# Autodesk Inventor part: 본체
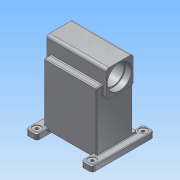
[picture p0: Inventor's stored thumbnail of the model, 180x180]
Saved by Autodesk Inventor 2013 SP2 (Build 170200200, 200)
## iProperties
Created: 2025-06
Part Number: 본체
Material: 알루미늄 6061
Document SubType Name: Modeling
Designer: a
Mass: 8501.84 g
Surface Area: 3573.04 cm^2
Volume: 3137.21 cm^3
Density: 2.71 g/cm^3
Author: a
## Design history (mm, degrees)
sketch "스케치2"
  geometry: L1 (-38, 48)-(38, 48); L2 (48, 38)-(48, -38); L3 (38, -48)-(-38, -48); L4 (-48, -38)-(-48, 38); L5 (-48, 48)-(48, -48); L6 (48, 48)-(-48, -48); L7 (-213, -55)-(-7, -55); L8 (-7, -55)-(-7, 70); L9 (-7, 70)-(-213, 70); L10 (-213, 70)-(-213, -55); A1 r 10 centre (38, 38) between (48, 38) and (38, 48); A2 r 10 centre (-38, 38) between (-38, 48) and (-48, 38); A3 r 10 centre (-38, -38) between (-48, -38) and (-38, -48); A4 r 10 centre (38, -38) between (38, -48) and (48, -38); 1 further point
  constraints: 20 end point, 8 point on circle, 8 point on line, 8 tangent, 4 centre point, 4 parallel, 3 equal radius, 2 horizontal, 2 midpoint, 2 perpendicular
  dimensions: "d0" = 96 distance of L6.start L5.end; "d2" = 96 distance of L5.start L6.start; "d3" = 10 radius of A1; "d18" = 206 distance of L7.start L7.end; "d20" = 261 distance between parallel lines of L10 L2; "d22" = 22 distance between parallel lines of L1 L9; "d23" = 7 distance between parallel lines of L3 L7
extrude "돌출1" new body sketch "스케치2" stored distance "d24" = 210; taper "d25" = 0 deg
extrude "돌출2" join sketch "스케치2" stored distance "d26" = 186; taper "d27" = 0 deg
sketch "스케치3"
  geometry: L1 (0, 0)-(0, 125) reference; L2 (0, 125)-(186, 125) reference; L3 (186, 125)-(186, 0) reference; L4 (186, 0)-(0, 0) reference; L5 (171, 165)-(211, 165); L6 (211, 165)-(211, -55); L7 (211, -55)-(171, -55); L8 (171, -55)-(171, 165); 1 further point
  constraints: 8 end point, 2 parallel, 1 horizontal, 1 perpendicular
  dimensions: "d28" = 40 distance of L5.start L5.end; "d30" = 220 distance of L5.end L6.end; "d31" = 118 distance from line of L6 point (93, 55); "d32" = 110 distance from line of point (93, 55) L5
extrude "돌출3" join sketch "스케치3" distance "d33" = 20; taper "d34" = 0 deg
fillet "모깎기1" dims "d35" = 10
sketch "스케치4"
  geometry: C1 r 38.5 at (0, 0); 1 further point
  constraints: 1 centre point, 1 coincident
  dimensions: "d37" = 77 diameter of C1
extrude "돌출4" cut sketch "스케치4" stored distance "d38" = 20; taper "d39" = 0 deg
sketch "스케치5"
  geometry: C1 r 38.5 at (0, 0) reference; C2 r 42.5 at (0, 0)
  constraints: 1 centre point, 1 coincident
  dimensions: "d40" = 85 diameter of C2
extrude "돌출5" cut sketch "스케치5" distance "d41" = 23; taper "d42" = 0 deg
sketch "스케치6"
  geometry: C1 r 38.5 at (0, 0) reference; C2 r 42.5 at (0, 0)
  constraints: 1 centre point, 1 coincident
  dimensions: "d43" = 85 diameter of C2
extrude "돌출6" cut sketch "스케치6" distance "d44" = 23; taper "d45" = 0 deg
node "작업 평면1"
fillet "모깎기2" dims "d47" = 1.1
fillet "모깎기3" dims "d48" = 1.1
chamfer "모따기1" distance "d49" = 1; stored, may be unused: second distance "d50" = 2, angle "d51" = 45 deg
chamfer "모따기2" distance "d52" = 1; stored, may be unused: second distance "d53" = 2, angle "d54" = 45 deg
sketch "스케치11"
  geometry: L1 (48, 38)-(48, -38) reference; L2 (38, -48)-(-7, -48) reference; L3 (-7, -48)-(-7, -55) reference; L4 (-7, -55)-(-213, -55) reference; L5 (-213, -55)-(-213, 70) reference; L6 (-213, 70)-(-7, 70) reference; L7 (-7, 70)-(-7, 48) reference; L8 (-7, 48)-(38, 48) reference; L9 (-110, -55)-(-110, 70); L10 (-24, -55)-(-24, 47); L11 (-24, 47)-(-79, 47); L12 (-24, -55)-(-110, -55); L13 (-79, 47)-(-79, 62); L14 (-80, 63)-(-83, 63); L15 (-83, 63)-(-83, 63); L16 (-86, 66)-(-110, 66); C1 r 38.5 at (0, 0) reference; A1 r 10 centre (38, 38) between (48, 38) and (38, 48) reference; A2 r 10 centre (38, -38) between (38, -48) and (48, -38) reference; A3 r 1 centre (-80, 62) between (-79, 62) and (-80, 63); A4 r 3 centre (-86, 63) between (-83, 63) and (-86, 66); 2 further points
  constraints: 16 end point, 5 perpendicular, 4 point on circle, 4 point on line, 4 tangent, 2 centre point, 2 midpoint, 1 collinear, 1 parallel
  dimensions: "d56" = 172 diameter of L10 L9; "d58" = 102 distance between parallel lines of L11 L12; "d64" = 16 distance of L11.end point (-79, 63); "d65" = 62 diameter of L13 L9; "d66" = 54 diameter of L15 L9; "d67" = 3 distance between parallel lines of L14 L16; "d68" = 1 radius of A3; "d69" = 3 radius of A4
revolve "회전1" sketch "스케치11" stored, may be unused: angle "d70" = 90 deg
sketch "스케치12"
  geometry: C1 r 86 at (93, -103) reference; 5 further points
  dimensions: "d71" = 150 distance of point (168, -28) point (18, -28); "d73" = 75 horizontal distance of C1.centre point (18, -28); "d76" = 150 distance of point (18, -178) point (18, -28); "d77" = 150 distance of point (168, -178) point (168, -28); "d78" = 75 horizontal distance of C1.centre point (18, -28); "d79" = 75 horizontal distance of C1.centre point (168, -178); "d80" = 75 horizontal distance of C1.centre point (18, -178); "d81" = 75 horizontal distance of C1.centre point (168, -178)
hole "구멍1" sketch "스케치12" at (18, -28), (168, -28), (168, -178), (18, -178) diameter "d82" = 6.647; stored, may be unused: countersink angle "d86" = 90 deg, drill point angle "d88" = 118 deg; dims "d83" = 16, "d84" = 4, "d85" = 2, "d87" = 18
chamfer "모따기3" distance "d89" = 1; stored, may be unused: second distance "d90" = 2, angle "d91" = 45 deg
sketch "스케치13"
  geometry: L1 (15, -226)-(-25, -226) reference; L2 (-25, -226)-(-25, -206) reference; L3 (-25, -206)-(0, -206) reference; L4 (0, -206)-(15, -206) reference; L5 (15, -206)-(15, -226) reference; L6 (0, -206)-(0, 0) reference; L7 (0, 0)-(186, 0) reference; L8 (186, 0)-(186, -206) reference; L9 (186, -206)-(211, -206) reference; L10 (211, -206)-(211, -226) reference; L11 (211, -226)-(171, -226) reference; L12 (171, -226)-(171, -206) reference; L13 (171, -206)-(186, -206) reference; L14 (171, -206)-(15, -206) reference; L15 (0, -199)-(186, -199); L16 (186, -199)-(186, -216); L17 (186, -216)-(0, -216); L18 (0, -216)-(0, -199); C1 r 87 at (93, -103) reference; C2 r 3.324 at (168, -178) reference; C3 r 3.324 at (18, -28) reference; C4 r 3.324 at (168, -28) reference; C5 r 3.324 at (18, -178) reference; 1 further point
  constraints: 8 end point, 2 parallel, 1 horizontal, 1 perpendicular, 1 point on line
  dimensions: "d92" = 186 distance between parallel lines of L16 L18; "d94" = 10 distance between parallel lines of L1 L17; "d95" = 17 distance between parallel lines of L17 L15
extrude "돌출7" join sketch "스케치13" distance "d96" = 15; taper "d97" = 0 deg
sketch "스케치14"
  geometry: A1 r 10 centre (38, 38) between (48, 38) and (38, 48) reference; A2 r 10 centre (-38, 38) between (-38, 48) and (-48, 38) reference; A3 r 10 centre (-38, -38) between (-48, -38) and (-38, -48) reference; A4 r 10 centre (38, -38) between (38, -48) and (48, -38) reference; 4 further points
  constraints: 4 coincident
hole "구멍2" sketch "스케치14" at (-38, 38), (38, 38), (38, -38), (-38, -38) diameter "d98" = 4.917; stored, may be unused: countersink angle "d102" = 90 deg, drill point angle "d104" = 118 deg; dims "d99" = 12, "d100" = 4, "d101" = 2, "d103" = 14
fillet "모깎기4" dims "d105" = 10
sketch "스케치15"
  geometry: 5 further points
  dimensions: "d106" = 196 distance of point (191, 35) point (-5, 35); "d108" = 98 horizontal distance of point (93, -55) point (191, 35); "d109" = 180 distance of point (191, -145) point (191, 35); "d110" = 90 vertical distance of point (93, -55) point (191, -145); "d111" = 180 distance of point (-5, 35) point (-5, -145); "d112" = 90 vertical distance of point (93, -55) point (-5, -145); "d113" = 196 distance of point (191, -145) point (-5, -145); "d114" = 98 horizontal distance of point (93, -55) point (-5, -145)
hole "구멍3" sketch "스케치15" at (191, 35), (-5, 35), (191, -145), (-5, -145) diameter "d115" = 11; stored, may be unused: countersink angle "d119" = 90 deg, drill point angle "d121" = 0 deg; dims "d116" = 12, "d117" = 28, "d118" = 2, "d120" = 14
sketch "스케치16"
  geometry: L1 (-171, -216)-(-15, -216); L2 (-15, -216)-(-15, -206); L3 (-15, -206)-(-171, -206); L4 (-171, -206)-(-171, -216); 1 further point
  constraints: 8 end point, 2 parallel, 1 horizontal, 1 perpendicular
extrude "돌출8" join sketch "스케치16" distance "d122" = 125; taper "d123" = 0 deg
fillet "모깎기5" dims "d124" = 3
fillet "모깎기6" dims "d125" = 3
fillet "모깎기7" dims "d126" = 3
fillet "모깎기8" dims "d127" = 3
fillet "모깎기9" dims "d128" = 3
fillet "모깎기10" dims "d129" = 3
fillet "모깎기11" dims "d130" = 3
fillet "모깎기12" dims "d131" = 3
sketch "스케치17"
  geometry: L1 (210, 10)-(0, 10) reference; 2 further points
  constraints: 1 vertical alignment, 1 other
  dimensions: "d132" = 30 distance from line of point (105, -20) L1
feature "엠보싱1" sketch "스케치17" dims "d133" = 0.5, "d134" = 0
node "솔리드1"
mirror "대칭1"
mirror "대칭2"
node "절단 모서리 투영1"
node "절단 모서리 투영4"
node "절단 모서리 투영5"
other parameters: "d46" = -42.5
